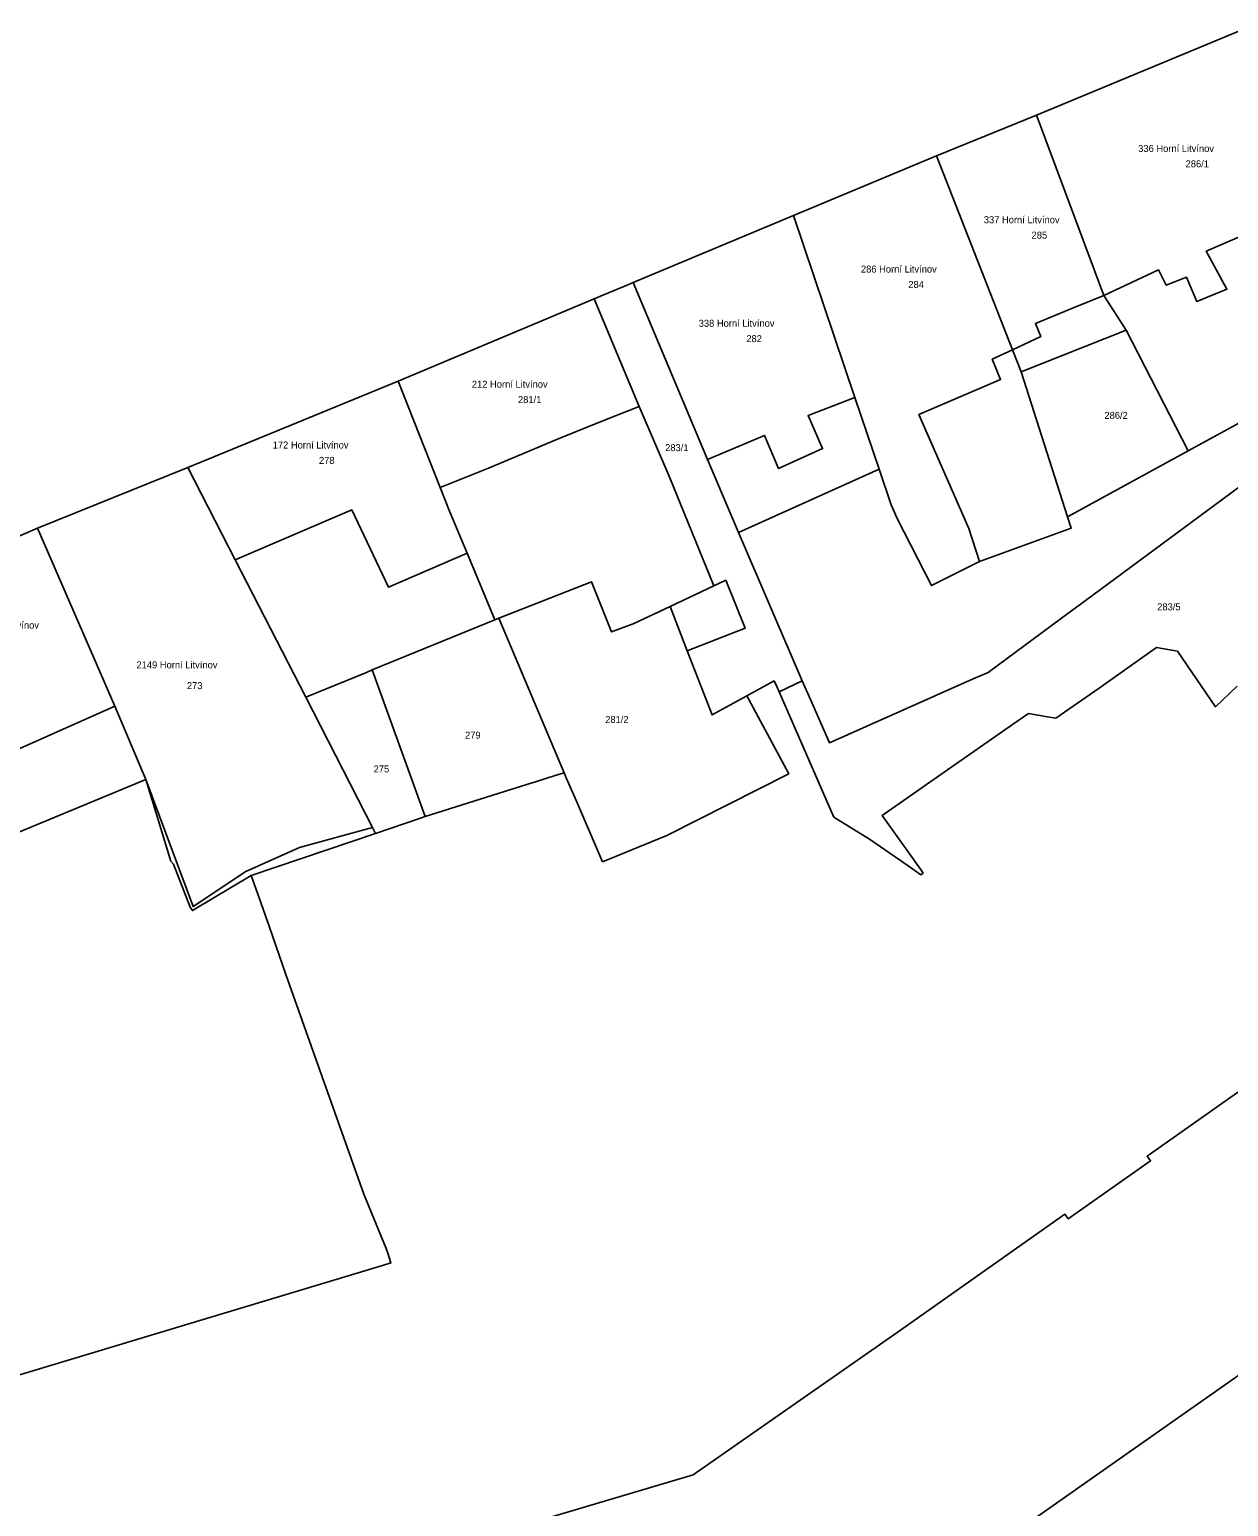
# Model space of a CAD drawing. Extents: x -792094 to -791524, y -979074 to -977761.
# Drawn here: x -791789.4 to -791703.6, y -978671 to -978565.4 of the extents above; entities that cross this region are included whole.
import ezdxf

# ---------------------------------------------------------------- set-up
doc = ezdxf.new("R2010")
doc.units = 0
doc.layers.add('katastr', color=7, linetype='Continuous')

msp = doc.modelspace()

# ---------------------------------------------------------------- linework, layer by layer
at = {"layer": 'katastr'}
for points in [[(-791875, -978639.29), (-791872.85, -978639.37), (-791872.15, -978635.76), (-791858.4, -978630.22), (-791845.69, -978624.63), (-791835.74, -978620.5), (-791824.02, -978615.86), (-791811.13, -978610.41), (-791798.34, -978605.15), (-791788.78, -978601.03), (-791778.04, -978596.71), (-791762.99, -978590.52), (-791748.97, -978584.64), (-791748.21, -978584.32), (-791746.55, -978583.63), (-791746.17, -978583.47), (-791734.69, -978578.66), (-791724.47, -978574.39), (-791717.3, -978571.49), (-791702.54, -978565.36)], [(-791687.73, -978586.95), (-791704.49, -978599.34), (-791713.28, -978605.83), (-791714.45, -978606.7), (-791715.51, -978607.48), (-791720.76, -978611.36), (-791721.85, -978611.83), (-791732.13, -978616.39), (-791733.49, -978613.3), (-791734.08, -978611.97), (-791735.72, -978612.76), (-791731.8, -978621.71), (-791729.25, -978623.29), (-791727.04, -978624.83), (-791726.25, -978625.38), (-791725.59, -978625.84), (-791725.42, -978625.72), (-791725.61, -978625.45), (-791728.34, -978621.6), (-791723.92, -978618.51), (-791718.95, -978615.04), (-791717.89, -978614.3), (-791717.06, -978614.44), (-791716.51, -978614.54), (-791716.08, -978614.61), (-791715.92, -978614.64), (-791712.83, -978612.48), (-791711.76, -978611.73), (-791708.72, -978609.59), (-791707.22, -978609.84), (-791704.5, -978613.82), (-791702.95, -978612.34)], [(-791791.18, -978661.95), (-791778.44, -978658.12), (-791764.1, -978653.8), (-791763.5, -978653.62), (-791763.73, -978652.92), (-791763.85, -978652.58), (-791765.44, -978648.7), (-791771.01, -978632.97), (-791772.2, -978629.6), (-791772.79, -978627.9), (-791773.5, -978625.89), (-791777.71, -978628.41), (-791777.87, -978628.17), (-791779.05, -978625.08), (-791779.24, -978624.86), (-791781.04, -978619.02), (-791790.81, -978623.08)], [(-791691.02, -978633.03), (-791709.39, -978645.99), (-791709.15, -978646.32), (-791715.04, -978650.46), (-791715.27, -978650.14), (-791727.27, -978658.6), (-791741.88, -978668.79), (-791758.03, -978673.58), (-791774.17, -978678.39), (-791785.37, -978681.63), (-791796.82, -978685.24), (-791800.29, -978685.11), (-791811.67, -978680.15), (-791829.06, -978672.54), (-791835.86, -978669.8), (-791850.39, -978659.23), (-791854.6, -978662.5), (-791863.96, -978650.65), (-791872.85, -978639.37), (-791875, -978639.29)], [(-791881.42, -978653.96), (-791871.15, -978665.14), (-791871.26, -978665.24), (-791862.45, -978674.63), (-791856.94, -978677.83), (-791848.49, -978682.67), (-791846.81, -978680.56), (-791821.21, -978694.27), (-791820.82, -978694.48), (-791818.06, -978696.66), (-791815.56, -978698.63), (-791808.15, -978705.53), (-791803.72, -978710.43), (-791799.83, -978717.1), (-791797.49, -978724.11), (-791797.3, -978725.09), (-791793.68, -978725.32), (-791777.44, -978728.19), (-791768.2, -978712.08), (-791752.21, -978696.33), (-791747.66, -978693.14), (-791700.66, -978660.13)], [(-791700.66, -978660.13), (-791747.66, -978693.14), (-791744.76, -978696.01), (-791749.71, -978699.55), (-791765.13, -978713.77), (-791776.32, -978734.03), (-791780.7, -978756.2)]]:
    msp.add_lwpolyline(points, dxfattribs=at)
for points in [[(-791702.54, -978565.36), (-791717.3, -978571.49), (-791712.49, -978584.39), (-791708.57, -978582.56), (-791708.03, -978583.65), (-791706.58, -978583.08), (-791705.84, -978584.81), (-791703.68, -978583.94), (-791705.16, -978581.22), (-791702.4, -978580.02), (-791699.02, -978578.54), (-791695.15, -978576.91)], [(-791691.93, -978586.33), (-791689.62, -978584.72), (-791693.18, -978580.04), (-791695.15, -978576.91), (-791702.54, -978565.36), (-791717.3, -978571.49), (-791712.49, -978584.39), (-791710.89, -978586.87), (-791706.46, -978595.5), (-791698.64, -978591.23), (-791692.7, -978587.03)], [(-791724.47, -978574.39), (-791719.02, -978588.29), (-791717, -978587.32), (-791717.38, -978586.39), (-791714.61, -978585.26), (-791712.49, -978584.39), (-791717.3, -978571.49)], [(-791710.89, -978586.87), (-791712.49, -978584.39), (-791717.3, -978571.49), (-791724.47, -978574.39), (-791719.02, -978588.29), (-791718.41, -978589.86)], [(-791734.69, -978578.66), (-791730.3, -978591.69), (-791728.57, -978596.82), (-791727.71, -978599.38), (-791727.27, -978600.35), (-791724.81, -978605.15), (-791721.38, -978603.43), (-791722.16, -978601.06), (-791725.72, -978592.91), (-791719.88, -978590.4), (-791720.47, -978588.95), (-791719.02, -978588.29), (-791724.47, -978574.39)], [(-791728.57, -978596.82), (-791727.71, -978599.38), (-791727.27, -978600.35), (-791724.81, -978605.15), (-791721.38, -978603.43), (-791714.82, -978601.04), (-791715.08, -978600.23), (-791718.41, -978589.86), (-791719.02, -978588.29), (-791724.47, -978574.39), (-791734.69, -978578.66), (-791730.3, -978591.69)], [(-791734.69, -978578.66), (-791746.17, -978583.47), (-791740.85, -978596.13), (-791736.77, -978594.4), (-791735.77, -978596.77), (-791732.61, -978595.35), (-791733.65, -978592.97), (-791730.3, -978591.69)], [(-791738.62, -978601.34), (-791728.57, -978596.82), (-791730.3, -978591.69), (-791734.69, -978578.66), (-791746.17, -978583.47), (-791740.85, -978596.13)], [(-791736.08, -978611.96), (-791735.89, -978612.38), (-791735.72, -978612.76), (-791734.08, -978611.97), (-791738.62, -978601.34), (-791740.85, -978596.13), (-791746.17, -978583.47), (-791746.55, -978583.63), (-791748.21, -978584.32), (-791748.97, -978584.64), (-791745.74, -978592.33), (-791743.55, -978597.43), (-791740.39, -978605.17), (-791739.54, -978604.77), (-791738.15, -978608.19), (-791742.31, -978609.83), (-791740.52, -978614.4), (-791738.04, -978613.04)], [(-791748.97, -978584.64), (-791762.99, -978590.52), (-791759.97, -978598.13), (-791756.53, -978596.75), (-791751.57, -978594.67), (-791748.34, -978593.37), (-791745.74, -978592.33)], [(-791740.39, -978605.17), (-791743.55, -978597.43), (-791745.74, -978592.33), (-791748.97, -978584.64), (-791762.99, -978590.52), (-791759.97, -978598.13), (-791759.3, -978599.82), (-791758.04, -978602.84), (-791756.07, -978607.59), (-791755.77, -978607.47), (-791749.14, -978604.89), (-791747.72, -978608.46), (-791746.16, -978607.89), (-791743.51, -978606.64)], [(-791706.46, -978595.5), (-791710.89, -978586.87), (-791718.41, -978589.86), (-791715.08, -978600.23)], [(-791758.04, -978602.84), (-791759.3, -978599.82), (-791759.97, -978598.13), (-791762.99, -978590.52), (-791778.04, -978596.71), (-791774.65, -978603.3), (-791766.3, -978599.74), (-791763.68, -978605.27)], [(-791765.26, -978611.36), (-791764.84, -978611.18), (-791756.07, -978607.59), (-791758.04, -978602.84), (-791759.3, -978599.82), (-791759.97, -978598.13), (-791762.99, -978590.52), (-791778.04, -978596.71), (-791774.65, -978603.3), (-791769.6, -978613.14)], [(-791774.65, -978603.3), (-791778.04, -978596.71), (-791788.78, -978601.03), (-791783.25, -978613.78), (-791781.04, -978619.02), (-791777.66, -978628.12), (-791773.89, -978625.62), (-791770.04, -978623.9), (-791764.81, -978622.47), (-791769.6, -978613.14)], [(-791781.04, -978619.02), (-791779.24, -978624.86), (-791779.05, -978625.08), (-791777.87, -978628.17), (-791777.71, -978628.41), (-791773.5, -978625.89), (-791764.61, -978622.88), (-791764.81, -978622.47), (-791769.6, -978613.14), (-791774.65, -978603.3), (-791778.04, -978596.71), (-791788.78, -978601.03), (-791783.25, -978613.78)], [(-791792.91, -978618.07), (-791783.25, -978613.78), (-791788.78, -978601.03), (-791798.34, -978605.15), (-791793.75, -978616.07)], [(-791790.81, -978623.08), (-791781.04, -978619.02), (-791783.25, -978613.78), (-791788.78, -978601.03), (-791798.34, -978605.15), (-791793.75, -978616.07), (-791792.91, -978618.07)], [(-791751.11, -978618.54), (-791750.95, -978618.91), (-791750.23, -978620.57), (-791748.36, -978624.91), (-791743.76, -978623.03), (-791735.04, -978618.61), (-791737.06, -978614.86), (-791737.92, -978613.26), (-791738.04, -978613.04), (-791740.52, -978614.4), (-791742.31, -978609.83), (-791743.51, -978606.64), (-791746.16, -978607.89), (-791747.72, -978608.46), (-791749.14, -978604.89), (-791755.77, -978607.47)], [(-791751.11, -978618.54), (-791755.77, -978607.47), (-791756.07, -978607.59), (-791764.84, -978611.18), (-791761.06, -978621.67), (-791754.93, -978619.74), (-791753.01, -978619.14), (-791751.76, -978618.75)], [(-791765.26, -978611.36), (-791769.6, -978613.14), (-791764.81, -978622.47), (-791764.61, -978622.88), (-791761.46, -978621.81), (-791761.06, -978621.67), (-791764.84, -978611.18)]]:
    msp.add_lwpolyline(points, close=True, dxfattribs=at)

# ---------------------------------------------------------------- texts
for s, p in [('336 Horní Litvínov', (-791710.03, -978574.12)), ('286/1', (-791706.64, -978575.22)), ('337 Horní Litvínov', (-791721.08, -978579.22)), ('285', (-791717.66, -978580.32)), ('286 Horní Litvínov', (-791729.87, -978582.75)), ('284', (-791726.48, -978583.85)), ('338 Horní Litvínov', (-791741.48, -978586.63)), ('282', (-791738.07, -978587.73)), ('212 Horní Litvínov', (-791757.71, -978590.99)), ('281/1', (-791754.41, -978592.09)), ('286/2', (-791712.45, -978593.22)), ('172 Horní Litvínov', (-791771.96, -978595.34)), ('283/1', (-791743.88, -978595.53)), ('278', (-791768.65, -978596.44)), ('283/5', (-791708.67, -978606.92)), ('171 Horní Litvínov', (-791794.11, -978608.23)), ('2149 Horní Litvínov', (-791781.71, -978611.07)), ('273', (-791778.1, -978612.56)), ('281/2', (-791748.17, -978614.98)), ('279', (-791758.2, -978616.1)), ('275', (-791764.74, -978618.52))]:
    msp.add_text(s, height=0.5, dxfattribs=at).set_placement(p)

doc.saveas('drawing.dxf')
